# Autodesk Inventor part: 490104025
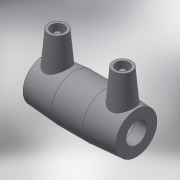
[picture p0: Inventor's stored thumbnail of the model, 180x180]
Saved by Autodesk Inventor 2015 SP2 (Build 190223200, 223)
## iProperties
Created: 2017-06
Part Number: 490104025
Material: Generic
Description: PLASSON COUPLER 25-25
Document SubType Name: Modeling
Designer: KIM
Mass: 55.0731 g
Surface Area: 148.067 cm^2
Volume: 55.0731 cm^3
Density: 1 g/cm^3
Appearance: Default
Author: KIM
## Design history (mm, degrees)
derived "490104.ipt"
feature "Solid1::490104.ipt"
tag "TaggingFeature1"
body "Solid1"
other parameters: "d0" = 82, "d1" = 25, "d2" = 36, "d4" = 27.33333, "d5" = 32.4, "d6" = 23.75, "d7" = 25, "d8" = 168 deg, "d10" = 16, "d11" = 5.33333, "d13" = 82, "d14" = 17.6296, "d17" = 23.75, "d18" = 25, "d19" = 3.52592, "d20" = 168 deg, "d22" = 33.84, "d23" = 36, "d24" = 32.8248, "d25" = 135 deg, "d26" = 32.8, "d27" = 135 deg, "d29" = 37, "d30" = 14, "d31" = 28.7, "d34" = 5 deg, "d35" = 15, "d39" = 5 deg, "d41" = 4, "d42" = 14, "d43" = 0, "d45" = 4, "d46" = 14, "d47" = 0, "d48" = 3, "d49" = 0, "d50" = 3, "d51" = 0, "d52" = 11.6, "d53" = 2.9, "d_" = 25, "L_" = 82, "D_" = 36, "A_" = 37, "d_2" = 12
